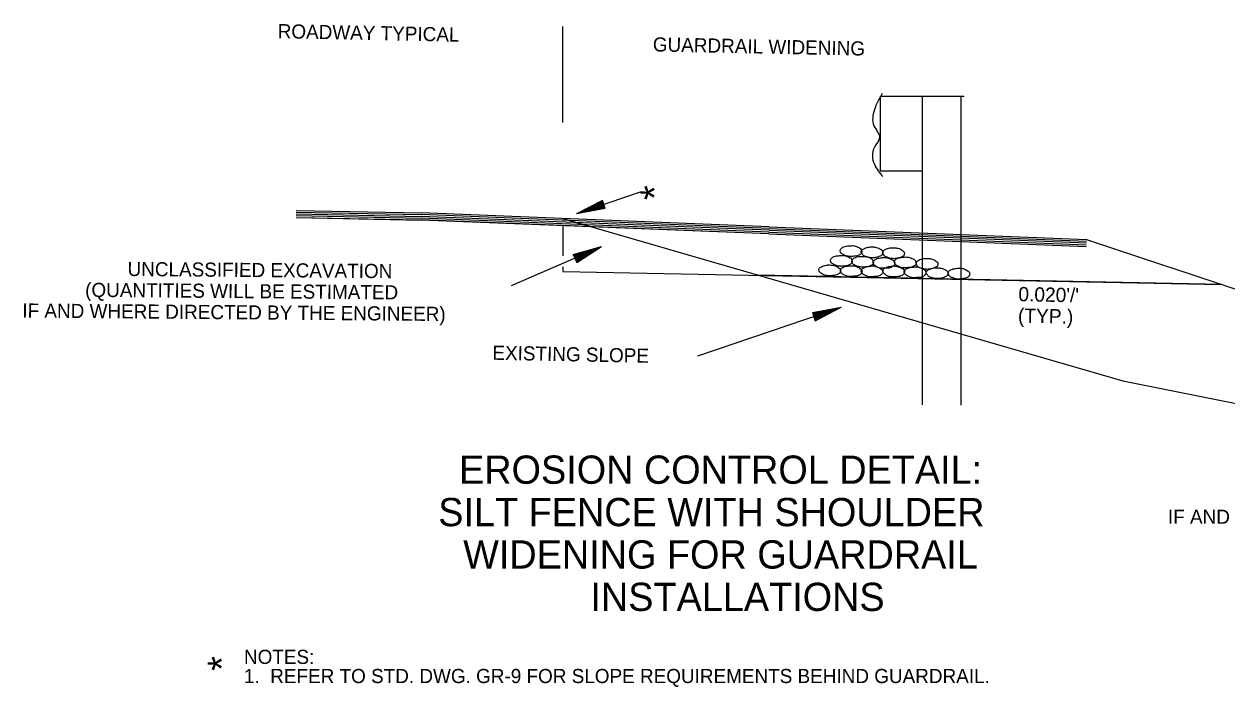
# Model space of a CAD drawing. Extents: x 1929624 to 1932072, y 596315 to 605533.
# Drawn here: x 1930601 to 1931112, y 605241 to 605523 of the extents above; entities that cross this region are included whole.
import ezdxf

# ---------------------------------------------------------------- set-up
doc = ezdxf.new("R2010")
doc.units = 0
doc.layers.add('Default', color=7, linetype='Continuous')
doc.layers.add('R_Border', color=7, linetype='Continuous')

msp = doc.modelspace()

# ---------------------------------------------------------------- linework, layer by layer
at = {"layer": 'Default'}
for p, q in [((1930964.72, 605492.28), (1930964.72, 605460.45)), ((1930964.72, 605492.28), (1931000.37, 605492.28)), ((1930982.56, 605492.28), (1930982.56, 605361.1)), ((1930998.94, 605492.14), (1930998.94, 605360.97)), ((1930964.72, 605460.45), (1930982.56, 605460.45)), ((1930862.9, 605451.4), (1930835.81, 605442.2)), ((1930716.81, 605443.72), (1930769.98, 605442.66)), ((1930846.84, 605447.99), (1930835.81, 605442.2)), ((1930848.05, 605444.54), (1930835.81, 605442.2)), ((1930846.97, 605447.71), (1930837.74, 605442.86)), ((1930847.97, 605444.8), (1930837.74, 605442.86)), ((1930847.08, 605447.37), (1930839.81, 605443.6)), ((1930847.83, 605445.12), (1930839.81, 605443.6)), ((1930847.13, 605447.1), (1930841.73, 605444.26)), ((1930847.73, 605445.42), (1930841.73, 605444.26)), ((1930847.25, 605446.84), (1930843.66, 605444.95)), ((1930847.61, 605445.73), (1930843.66, 605444.95)), ((1930847.34, 605446.53), (1930845.62, 605445.64)), ((1930847.57, 605446.03), (1930845.62, 605445.64)), ((1930848.05, 605444.54), (1930846.84, 605447.99)), ((1930716.81, 605442.98), (1930769.98, 605441.92)), ((1930716.84, 605442.24), (1930769.98, 605441.18)), ((1930716.86, 605441.5), (1930769.98, 605440.44)), ((1930716.89, 605440.76), (1930769.93, 605439.71)), ((1930716.89, 605440.67), (1930769.98, 605439.61)), ((1930917.5, 605433.8), (1930769.88, 605439.71)), ((1930917.55, 605435.28), (1930769.93, 605441.18)), ((1930917.55, 605434.54), (1930769.93, 605440.44)), ((1930917.6, 605436.75), (1930769.98, 605442.66)), ((1930917.6, 605436.02), (1930769.98, 605441.92)), ((1930917.5, 605433.7), (1930769.98, 605439.61)), ((1930917.48, 605433.8), (1931052.14, 605428.41)), ((1930917.5, 605434.54), (1931052.16, 605429.15)), ((1930917.54, 605435.28), (1931052.19, 605429.89)), ((1930917.56, 605436.02), (1931052.22, 605430.63)), ((1930917.6, 605436.75), (1931052.26, 605431.37)), ((1930834.46, 605424.93), (1930846.42, 605428.41)), ((1930835.98, 605421.61), (1930846.42, 605428.41)), ((1931052.26, 605431.37), (1931287.27, 605353.24)), ((1930808.18, 605411.89), (1930840.18, 605425.68)), ((1930834.46, 605424.93), (1930835.98, 605421.61)), ((1930834.56, 605424.68), (1930844.56, 605427.58)), ((1930834.73, 605424.38), (1930842.57, 605426.64)), ((1930834.85, 605424.09), (1930840.72, 605425.8)), ((1930835, 605423.79), (1930838.87, 605424.94)), ((1930835.07, 605423.49), (1930836.98, 605424.07)), ((1930835.34, 605423.02), (1930836.98, 605424.07)), ((1930835.46, 605422.72), (1930838.87, 605424.94)), ((1930835.61, 605422.47), (1930840.72, 605425.8)), ((1930835.69, 605422.2), (1930842.57, 605426.64)), ((1930835.83, 605421.88), (1930844.56, 605427.58)), ((1930887.28, 605381.99), (1930948.19, 605402.67)), ((1930935.95, 605400.34), (1930948.19, 605402.67)), ((1930935.95, 605400.34), (1930937.16, 605396.88)), ((1930936.03, 605400.08), (1930946.26, 605402.01)), ((1930936.17, 605399.76), (1930944.19, 605401.28)), ((1930936.27, 605399.46), (1930942.27, 605400.61)), ((1930936.39, 605399.14), (1930940.34, 605399.93)), ((1930936.43, 605398.84), (1930938.38, 605399.24)), ((1930936.66, 605398.34), (1930938.38, 605399.24)), ((1930936.75, 605398.04), (1930940.34, 605399.93)), ((1930936.87, 605397.78), (1930942.27, 605400.61)), ((1930936.92, 605397.5), (1930944.19, 605401.28)), ((1930937.03, 605397.17), (1930946.26, 605402.01)), ((1930937.16, 605396.88), (1930948.19, 605402.67))]:
    msp.add_line(p, q, dxfattribs=at)
for points in [[(1930965.58, 605493.32), (1930962.23, 605486.4), (1930962.06, 605479.66), (1930964.47, 605474.47), (1930962.23, 605470.53), (1930962.23, 605463.28), (1930965.78, 605458.04)], [(1930952.47, 605428.74), (1930950.84, 605428.64), (1930948.87, 605428.05), (1930947.84, 605427.12), (1930947.69, 605426.58), (1930948.19, 605425.59), (1930948.78, 605425.15), (1930949.91, 605424.61), (1930951.48, 605424.16), (1930952.32, 605424.16), (1930953.5, 605424.26), (1930954.83, 605424.41), (1930955.86, 605424.8), (1930956.75, 605425.64), (1930956.9, 605426.28), (1930956.6, 605427.17), (1930955.96, 605427.76), (1930955.27, 605428.15), (1930954.19, 605428.59), (1930953.5, 605428.74), (1930952.47, 605428.74)], [(1930948.39, 605424.63), (1930946.67, 605424.44), (1930944.75, 605423.94), (1930943.76, 605423.01), (1930943.62, 605422.47), (1930944.11, 605421.43), (1930944.7, 605420.99), (1930945.78, 605420.4), (1930947.36, 605420.01), (1930948.14, 605420.01), (1930949.37, 605420.11), (1930950.75, 605420.2), (1930951.79, 605420.7), (1930952.67, 605421.53), (1930952.82, 605422.17), (1930952.52, 605423.06), (1930951.79, 605423.65), (1930951.1, 605423.94), (1930950.01, 605424.39), (1930949.37, 605424.58), (1930948.39, 605424.63)], [(1930957.32, 605424.21), (1930955.7, 605424.16), (1930953.73, 605423.53), (1930952.75, 605422.59), (1930952.6, 605422.05), (1930953.14, 605421.02), (1930953.68, 605420.57), (1930954.76, 605420.08), (1930956.34, 605419.69), (1930957.17, 605419.59), (1930958.35, 605419.69), (1930959.68, 605419.93), (1930960.72, 605420.33), (1930961.7, 605421.11), (1930961.85, 605421.75), (1930961.55, 605422.64), (1930960.82, 605423.23), (1930960.13, 605423.67), (1930959.04, 605424.02), (1930958.35, 605424.16), (1930957.32, 605424.21)], [(1930961.28, 605428.22), (1930959.66, 605428.12), (1930957.74, 605427.43), (1930956.76, 605426.64), (1930956.61, 605426.1), (1930957.15, 605425.07), (1930957.59, 605424.53), (1930958.77, 605424.03), (1930960.25, 605423.69), (1930961.09, 605423.59), (1930962.32, 605423.64), (1930963.69, 605423.89), (1930964.68, 605424.33), (1930965.71, 605425.12), (1930965.86, 605425.76), (1930965.56, 605426.64), (1930964.83, 605427.28), (1930964.09, 605427.63), (1930963.01, 605427.97), (1930962.32, 605428.12), (1930961.28, 605428.22)], [(1930966.42, 605423.71), (1930964.79, 605423.57), (1930962.82, 605423.02), (1930961.79, 605422.09), (1930961.64, 605421.55), (1930962.18, 605420.56), (1930962.73, 605420.12), (1930963.86, 605419.48), (1930965.38, 605419.14), (1930966.22, 605419.14), (1930967.4, 605419.24), (1930968.83, 605419.28), (1930969.81, 605419.78), (1930970.75, 605420.61), (1930970.89, 605421.25), (1930970.6, 605422.14), (1930969.91, 605422.73), (1930969.17, 605423.07), (1930968.14, 605423.42), (1930967.45, 605423.71), (1930966.42, 605423.71)], [(1930970.46, 605427.85), (1930968.84, 605427.8), (1930966.87, 605427.11), (1930965.88, 605426.22), (1930965.74, 605425.63), (1930966.28, 605424.65), (1930966.82, 605424.21), (1930967.9, 605423.71), (1930969.48, 605423.27), (1930970.31, 605423.22), (1930971.49, 605423.32), (1930972.82, 605423.57), (1930973.86, 605423.96), (1930974.84, 605424.75), (1930974.99, 605425.34), (1930974.69, 605426.22), (1930973.95, 605426.81), (1930973.26, 605427.31), (1930972.18, 605427.65), (1930971.49, 605427.8), (1930970.46, 605427.85)], [(1930975.37, 605423.94), (1930973.75, 605423.75), (1930971.83, 605423.25), (1930970.85, 605422.32), (1930970.7, 605421.78), (1930971.24, 605420.74), (1930971.78, 605420.3), (1930972.86, 605419.71), (1930974.44, 605419.32), (1930975.22, 605419.32), (1930976.46, 605419.42), (1930977.78, 605419.51), (1930978.87, 605420.01), (1930979.8, 605420.84), (1930979.95, 605421.48), (1930979.65, 605422.37), (1930978.92, 605422.96), (1930978.18, 605423.25), (1930977.14, 605423.75), (1930976.41, 605423.89), (1930975.37, 605423.94)], [(1930984.67, 605423.3), (1930983.05, 605423.25), (1930981.08, 605422.61), (1930980.1, 605421.68), (1930979.95, 605421.14), (1930980.49, 605420.11), (1930981.03, 605419.66), (1930982.11, 605419.17), (1930983.69, 605418.78), (1930984.53, 605418.68), (1930985.71, 605418.78), (1930987.03, 605419.02), (1930988.07, 605419.42), (1930989.05, 605420.2), (1930989.2, 605420.84), (1930988.9, 605421.73), (1930988.17, 605422.32), (1930987.48, 605422.76), (1930986.39, 605423.11), (1930985.71, 605423.25), (1930984.67, 605423.3)], [(1930943.37, 605420.54), (1930941.75, 605420.49), (1930939.78, 605419.8), (1930938.84, 605418.92), (1930938.7, 605418.33), (1930939.19, 605417.34), (1930939.78, 605416.9), (1930940.81, 605416.41), (1930942.44, 605415.96), (1930943.22, 605415.91), (1930944.45, 605416.01), (1930945.78, 605416.26), (1930946.82, 605416.65), (1930947.75, 605417.44), (1930947.9, 605418.03), (1930947.6, 605418.92), (1930946.86, 605419.51), (1930946.18, 605420), (1930945.09, 605420.34), (1930944.4, 605420.49), (1930943.37, 605420.54)], [(1930952.47, 605420.25), (1930950.85, 605420.11), (1930948.88, 605419.51), (1930947.95, 605418.63), (1930947.8, 605418.04), (1930948.29, 605417.05), (1930948.78, 605416.61), (1930949.92, 605416.12), (1930951.44, 605415.63), (1930952.28, 605415.63), (1930953.51, 605415.73), (1930954.89, 605415.92), (1930955.87, 605416.27), (1930956.85, 605417.15), (1930957, 605417.74), (1930956.71, 605418.63), (1930955.97, 605419.22), (1930955.23, 605419.66), (1930954.2, 605420.06), (1930953.51, 605420.2), (1930952.47, 605420.25)], [(1930961.32, 605420.12), (1930959.7, 605419.92), (1930957.73, 605419.38), (1930956.75, 605418.5), (1930956.6, 605417.91), (1930957.14, 605416.92), (1930957.68, 605416.48), (1930958.76, 605415.89), (1930960.29, 605415.5), (1930961.13, 605415.5), (1930962.36, 605415.59), (1930963.69, 605415.69), (1930964.72, 605416.14), (1930965.7, 605417.02), (1930965.85, 605417.61), (1930965.56, 605418.5), (1930964.82, 605419.09), (1930964.08, 605419.43), (1930963, 605419.83), (1930962.36, 605420.07), (1930961.32, 605420.12)], [(1930970.58, 605420.13), (1930968.91, 605419.93), (1930966.94, 605419.39), (1930965.96, 605418.51), (1930965.81, 605417.92), (1930966.35, 605416.93), (1930966.89, 605416.49), (1930968.02, 605415.85), (1930969.55, 605415.5), (1930970.34, 605415.5), (1930971.57, 605415.55), (1930972.94, 605415.7), (1930973.98, 605416.14), (1930974.91, 605417.03), (1930975.06, 605417.62), (1930974.77, 605418.51), (1930974.03, 605419.1), (1930973.29, 605419.44), (1930972.26, 605419.79), (1930971.62, 605419.98), (1930970.58, 605420.13)], [(1930979.65, 605419.76), (1930977.93, 605419.56), (1930976.06, 605419.07), (1930975.03, 605418.14), (1930974.88, 605417.6), (1930975.42, 605416.56), (1930975.96, 605416.12), (1930977.09, 605415.53), (1930978.62, 605415.14), (1930979.41, 605415.14), (1930980.64, 605415.23), (1930982.06, 605415.33), (1930983.05, 605415.82), (1930983.98, 605416.66), (1930984.13, 605417.3), (1930983.84, 605418.19), (1930983.1, 605418.78), (1930982.41, 605419.07), (1930981.33, 605419.47), (1930980.69, 605419.71), (1930979.65, 605419.76)], [(1930988.93, 605419.38), (1930987.31, 605419.28), (1930985.39, 605418.6), (1930984.4, 605417.81), (1930984.25, 605417.27), (1930984.8, 605416.23), (1930985.24, 605415.69), (1930986.42, 605415.2), (1930987.9, 605414.86), (1930988.73, 605414.76), (1930989.96, 605414.81), (1930991.34, 605415.05), (1930992.32, 605415.5), (1930993.36, 605416.28), (1930993.51, 605416.92), (1930993.21, 605417.81), (1930992.47, 605418.45), (1930991.73, 605418.79), (1930990.65, 605419.14), (1930989.96, 605419.28), (1930988.93, 605419.38)], [(1930998.18, 605419.19), (1930996.56, 605419.05), (1930994.59, 605418.46), (1930993.65, 605417.57), (1930993.51, 605416.98), (1930994, 605416), (1930994.49, 605415.55), (1930995.62, 605415.06), (1930997.15, 605414.57), (1930997.98, 605414.57), (1930999.21, 605414.67), (1931000.59, 605414.86), (1931001.58, 605415.21), (1931002.56, 605416.09), (1931002.71, 605416.69), (1931002.41, 605417.57), (1931001.67, 605418.16), (1931000.94, 605418.6), (1930999.9, 605419), (1930999.21, 605419.15), (1930998.18, 605419.19)]]:
    msp.add_spline(points, degree=3, dxfattribs=at)
at = {"layer": 'R_Border'}
for p, q in [((1930830.08, 605481.03), (1930830.08, 605521.81)), ((1931109.71, 605412.27), (1930913.02, 605416.18))]:
    msp.add_line(p, q, dxfattribs=at)
for points in [[(1930830.08, 605440.25), (1931067.62, 605371.32), (1931172.51, 605350.45), (1931225.36, 605348.85), (1931399.81, 605373.56)], [(1930830.08, 605437.2), (1930830.08, 605424.36)], [(1930830.08, 605419.76), (1930830.08, 605417.83), (1931109.71, 605412.27)]]:
    msp.add_lwpolyline(points, dxfattribs=at)

# ---------------------------------------------------------------- texts
at = {"layer": 'Default'}
for s, height, rotation, p in [('ROADWAY TYPICAL', 6, 358.8537, (1930708.99, 605516.85)), ('GUARDRAIL WIDENING', 6, 358.8537, (1930868.18, 605511.23)), ('*', 12, 90, (1930874.91, 605448.14)), ('UNCLASSIFIED EXCAVATION', 6, 359.527, (1930645.3, 605415.86)), ('(QUANTITIES WILL BE ESTIMATED', 6, 359.527, (1930627.29, 605407.01)), ("0.020'/'", 6.075, 358.8537, (1931023.31, 605405.17)), ('IF AND WHERE DIRECTED BY THE ENGINEER)', 6, 359.527, (1930600.65, 605398.23)), ('(TYP.)', 6.075, 358.8537, (1931023.13, 605396.06)), ('EXISTING SLOPE', 6, 358.8537, (1930800.1, 605380.32)), ('EROSION CONTROL DETAIL:', 12, 360, (1930785.98, 605327.65)), ('SILT FENCE WITH SHOULDER', 12, 360, (1930777.17, 605309.65)), (' WIDENING FOR GUARDRAIL', 12, 360, (1930783.28, 605291.65)), (' INSTALLATIONS ', 12, 360, (1930837.28, 605273.65)), ('*', 12, 90, (1930691.3, 605248.24))]:
    msp.add_text(s, height=height, rotation=rotation, dxfattribs=at).set_placement(p)
for s, p in [('IF AND WHERE DIRECTED BY THE ENGINEER)', (1931086.82, 605310.65)), ('NOTES:', (1930694.71, 605251.17)), ('1.  REFER TO STD. DWG. GR-9 FOR SLOPE REQUIREMENTS BEHIND GUARDRAIL.', (1930694.71, 605243.04))]:
    msp.add_text(s, height=6, dxfattribs=at).set_placement(p)

doc.saveas('drawing.dxf')
